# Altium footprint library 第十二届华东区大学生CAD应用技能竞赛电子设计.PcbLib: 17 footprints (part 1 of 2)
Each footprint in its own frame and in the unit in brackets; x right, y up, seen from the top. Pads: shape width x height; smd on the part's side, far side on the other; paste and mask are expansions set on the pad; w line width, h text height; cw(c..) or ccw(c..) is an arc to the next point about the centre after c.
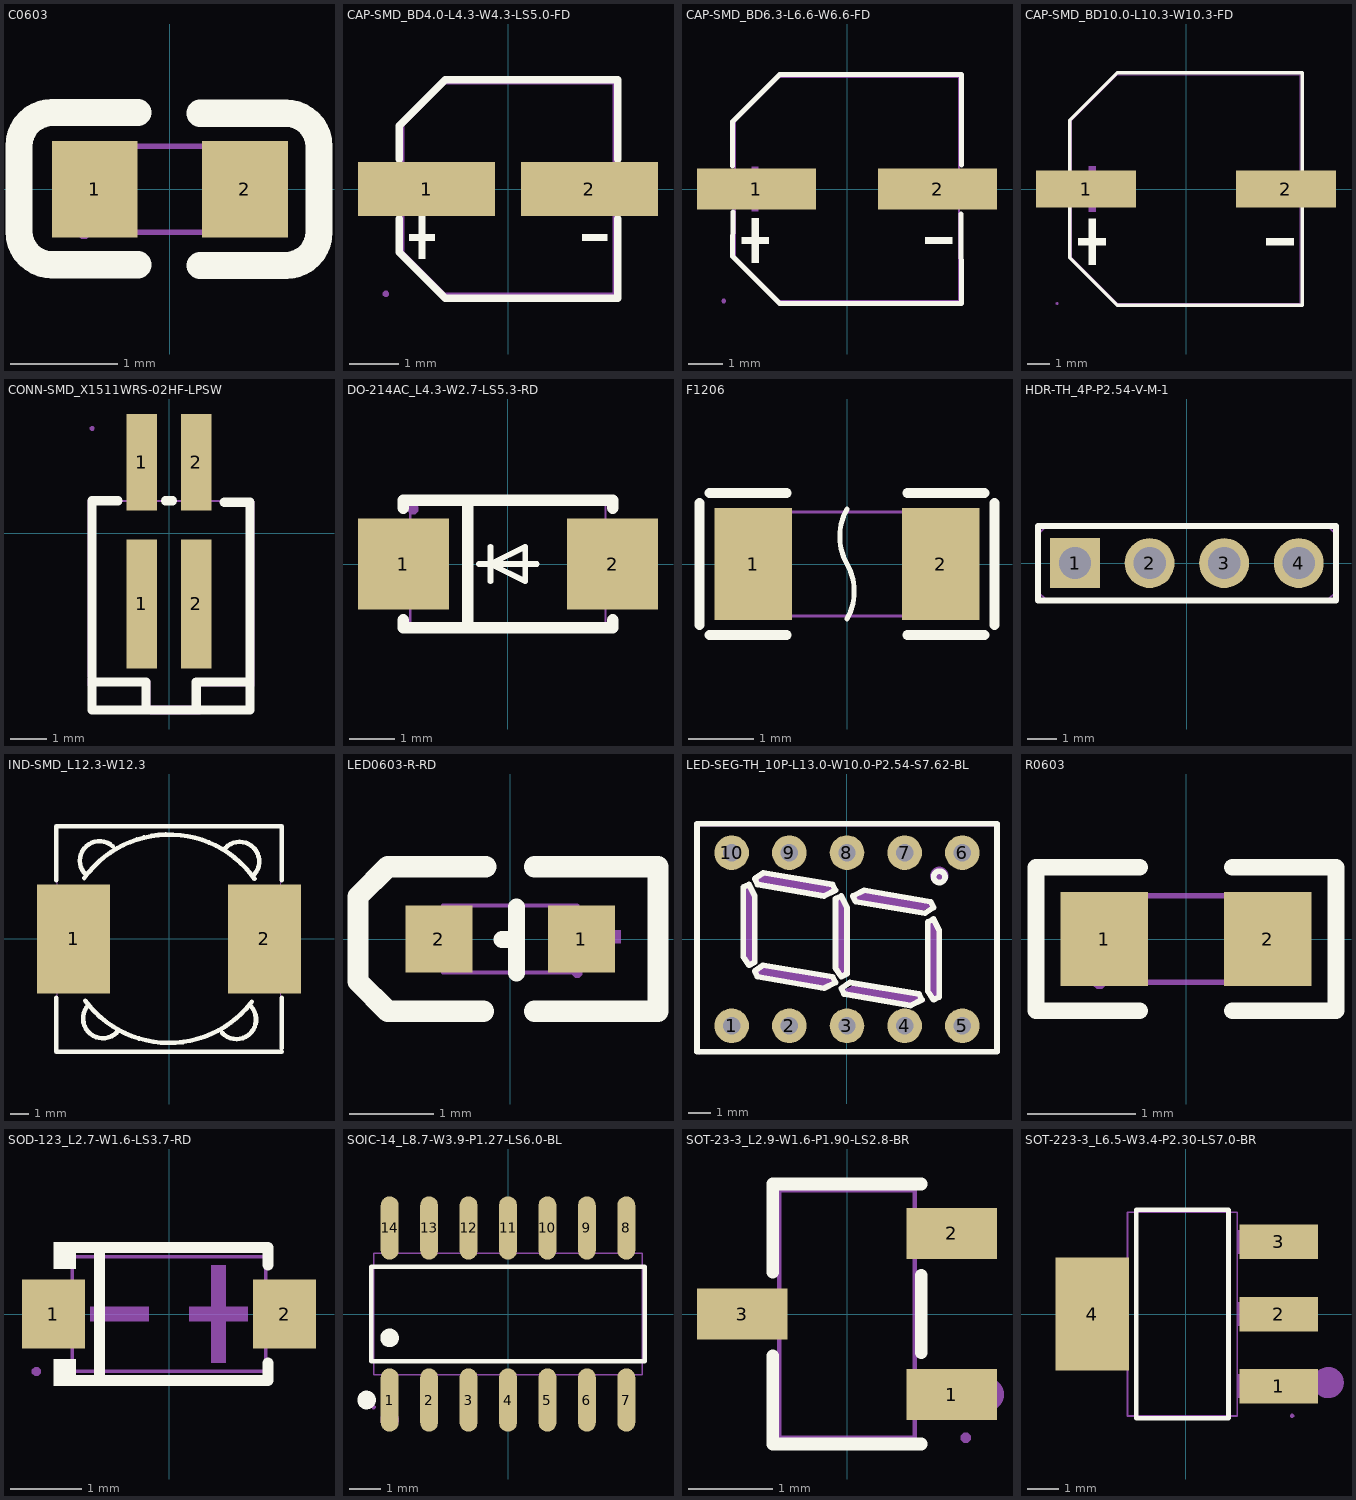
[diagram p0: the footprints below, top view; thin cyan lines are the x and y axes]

## C0603 [mm]
pads (2):
  rect 0.8x0.9 smd mask+0.051: 1(-0.7,0) 2(0.7,0)
Top Overlay:
  lines w0.254: -0.296,-0.704 -1.096,-0.704 cw(c-1.096,-0.394) -1.406,-0.394 -1.405,0.406 cw(c-1.096,0.406) -1.096,0.715 -0.296,0.715 ; 0.28,-0.71 1.08,-0.71 ccw(c1.08,-0.4) 1.39,-0.4 1.39,0.4 ccw(c1.08,0.4) 1.08,0.71 0.28,0.71
Mechanical 15:
  region: -0.74,-0.4 -0.74,-0.375 -0.775,-0.34 -0.825,-0.34 -0.86,-0.375 -0.86,-0.4 -0.86,-0.425 -0.825,-0.46 -0.775,-0.46 -0.74,-0.425
  region: -0.8,-0.4 -0.8,0.4 -0.5,0.4 -0.5,-0.4
  region: 0.8,-0.4 0.8,0.4 0.5,0.4 0.5,-0.4
  lines w0.051: -0.8,-0.4 -0.8,0.4 0.8,0.4 0.8,-0.4 -0.8,-0.4

## CAP-SMD_BD4.0-L4.3-W4.3-LS5.0-FD [mil]
pads (2):
  rect 110.2x43.3 smd mask+2: 1(-65.4,0) 2(65.4,0)
Top Overlay:
  region: 79.9,-36.4 79.9,-41.5 59.6,-41.5 59.6,-36.4
  region: -79.2,-36.4 -79.2,-41.5 -58.9,-41.5 -58.9,-36.4
  region: -71.6,-22 -71.6,-55.9 -66.5,-55.9 -66.5,-22
  lines w6: -87.3,-23.9 -87.3,-50.8 -50.4,-87.6 88,-87.6 88,-23.9 ; -87.3,23.9 -87.3,50.8 -50.4,87.6 88,87.6 88,23.9
Mechanical 6:
  region: 79.9,2.5 79.9,-2.5 59.6,-2.5 59.6,2.5
  region: -79.2,2.5 -79.2,-2.5 -58.9,-2.5 -58.9,2.5
  region: -71.6,16.9 -71.6,-16.9 -66.5,-16.9 -66.5,16.9
Mechanical 15:
  region: -100.5,-84.3 -100.5,-85.29 -99.09,-86.7 -97.11,-86.7 -95.7,-85.29 -95.7,-84.3 -95.7,-83.31 -97.11,-81.9 -99.09,-81.9 -100.5,-83.31
  region: -98.1,12.8 -19.3,12.8 -19.3,-12.8 -98.1,-12.8
  region: 20,12.8 98.8,12.8 98.8,-12.8 20,-12.8
  lines w2: -84.3,-50.4 -50.4,-84.3 85,-84.3 85,85 -50.4,85 -84.3,51.1 -84.3,-50.4

## CAP-SMD_BD6.3-L6.6-W6.6-FD [mm]
pads (2):
  rect 3.5x1.2 smd mask+0.051: 1(-2.67,0) 2(2.67,0)
Top Overlay:
  region: 3.102,-1.419 3.102,-1.617 2.31,-1.617 2.31,-1.419
  region: -3.102,-1.419 -3.102,-1.617 -2.31,-1.617 -2.31,-1.419
  region: -2.805,-0.858 -2.805,-2.178 -2.607,-2.178 -2.607,-0.858
  lines w0.152: -3.376,0.686 -3.376,1.98 -1.98,3.376 3.376,3.376 3.369,0.708 ; -3.362,-0.686 -3.376,-1.981 -1.981,-3.376 3.376,-3.376 3.356,-0.739
Mechanical 6:
  region: 3.102,0.099 3.102,-0.099 2.31,-0.099 2.31,0.099
  region: -3.102,0.099 -3.102,-0.099 -2.31,-0.099 -2.31,0.099
  region: -2.81,0.66 -2.81,-0.66 -2.612,-0.66 -2.612,0.66
Mechanical 15:
  region: -3.634,-3.24 -3.659,-3.24 -3.694,-3.275 -3.694,-3.325 -3.659,-3.36 -3.634,-3.36 -3.609,-3.36 -3.574,-3.325 -3.574,-3.275 -3.609,-3.24
  region: 1.067,0.325 3.667,0.325 3.667,-0.325 1.067,-0.325
  region: -3.634,0.325 -1.034,0.325 -1.034,-0.325 -3.634,-0.325
  lines w0.051: -3.3,-1.98 -1.98,-3.3 3.3,-3.3 3.3,3.3 -1.98,3.3 -3.3,1.98 -3.3,-1.98

## CAP-SMD_BD10.0-L10.3-W10.3-FD [mm]
pads (2):
  rect 4.5x1.65 smd mask+0.051: 1(-4.5,0) 2(4.5,0)
Top Overlay:
  region: 4.841,-2.214 4.841,-2.523 3.605,-2.523 3.605,-2.214
  region: -4.841,-2.214 -4.841,-2.523 -3.605,-2.523 -3.605,-2.214
  region: -4.378,-1.339 -4.378,-3.399 -4.068,-3.399 -4.068,-1.339
  lines w0.152: -5.226,-0.852 -5.226,-3.09 -3.09,-5.226 5.226,-5.226 5.226,-0.852 ; -5.226,0.852 -5.226,3.09 -3.09,5.226 5.226,5.226 5.226,0.852
Mechanical 6:
  region: 4.841,0.155 4.841,-0.155 3.605,-0.155 3.605,0.155
  region: -4.841,0.155 -4.841,-0.155 -3.605,-0.155 -3.605,0.155
  region: -4.378,1.03 -4.378,-1.03 -4.068,-1.03 -4.068,1.03
Mechanical 15:
  region: -5.74,-5.15 -5.74,-5.125 -5.775,-5.09 -5.825,-5.09 -5.86,-5.125 -5.86,-5.15 -5.86,-5.175 -5.825,-5.21 -5.775,-5.21 -5.74,-5.175
  region: -5.8,0.45 -2.3,0.45 -2.3,-0.45 -5.8,-0.45
  region: 2.3,0.45 5.8,0.45 5.8,-0.45 2.3,-0.45
  lines w0.051: -5.15,-3.09 -3.09,-5.15 5.15,-5.15 5.15,5.15 -3.09,5.15 -5.15,3.09 -5.15,-3.09

## CONN-SMD_X1511WRS-02HF-LPSW [mm]
pads (4):
  rect 0.85x3.55 smd mask+0.051: 1(-0.75,-1.95) 2(0.75,-1.95)
  rect 0.85x2.65 smd mask+0.051: 1(-0.75,1.95) 2(0.75,1.95)
Top Overlay:
  lines w0.254: -2.116,-4.87 2.184,-4.87 ; -2.116,-4.826 -2.116,0.889 ; -2.116,-4.101 -0.63,-4.101 -0.63,-4.86 ; -0.094,0.889 0.094,0.889 ; 0.75,-4.72 0.75,-4.1 2.09,-4.1 ; 1.519,0.844 2.229,0.844 2.229,-4.871 ; -2.116,0.889 -1.406,0.889 -2.116,0.889
Mechanical 6:
  region: 2.12,-4 0.71,-4 0.64,-4.07 0.64,-4.98 0.86,-4.98 0.86,-4.22 0.87,-4.21 2.35,-4.21 2.35,-4
  region: 2.34,-3.98 2.34,0.87 2.25,0.96 1.49,0.96 1.44,0.91 1.44,0.79 1.49,0.74 2.11,0.74 2.12,0.73 2.12,-3.99 2.34,-3.99
  region: -2.23,-3.94 -2.23,0.91 -2.14,1 -1.38,1 -1.33,0.95 -1.33,0.83 -1.38,0.78 -2,0.78 -2.01,0.77 -2.01,-3.95 -2.23,-3.95
  region: -2,-3.99 -0.59,-3.99 -0.52,-4.06 -0.52,-4.97 -0.74,-4.97 -0.74,-4.21 -0.75,-4.2 -2.23,-4.2 -2.23,-3.99
  region: -0.51,-4.75 0.64,-4.75 0.64,-4.97 0.63,-4.98 -0.52,-4.98 -0.52,-4.76 -0.53,-4.75
Mechanical 15:
  region: -2.116,2.939 -2.141,2.939 -2.176,2.904 -2.176,2.854 -2.141,2.819 -2.116,2.819 -2.091,2.819 -2.056,2.854 -2.056,2.904 -2.091,2.939
  region: 0.55,2.879 0.95,2.879 0.95,0.779 0.55,0.779
  region: -0.95,2.879 -0.55,2.879 -0.55,0.779 -0.95,0.779
  region: 0.55,-0.7 0.95,-0.7 0.95,-3.2 0.55,-3.2
  region: -0.95,-0.7 -0.55,-0.7 -0.55,-3.2 -0.95,-3.2
  lines w0.051: -2.116,-4.871 -2.116,0.879 2.184,0.879 2.184,-4.871 -2.116,-4.871

## DO-214AC_L4.3-W2.7-LS5.3-RD [mil]
pads (2):
  rect 78.7x78.7 smd mask+2: 1(-90.5,0) 2(90.6,0)
Top Overlay:
  lines w5: -25,0 25,0 ; -15,-15 -15,0 ; -15,15 -15,0 ; -15,0 15,15 15,0 15,-15 -15,0
  lines w10: -90.5,-48.5 -90.5,-55.1 90.6,-55.1 90.6,-48.5 ; -90.5,48.5 -90.5,55.1 90.6,55.1 90.6,48.5 ; -35,-55.1 -35,55.1
Mechanical 6:
  region: 117.9,1.1 63.7,1.1 63.7,5.3 67.7,5.6 117.6,5.5 117.7,5.7 117.7,1.3 117.8,1.2
  region: 89.8,17.6 89.8,-16.7 89.9,-16.8 94.1,-16.8 94.3,-16.6 94.3,17.6 94.1,17.8 89.5,17.8
  region: -117.3,-6.2 -117.5,-5.5 -117.5,3 -63.8,2.9 -63.4,2.1 -63.4,-6.4
Mechanical 15:
  region: -86.9,47.6 -86.9,45.65 -84.15,42.9 -80.25,42.9 -77.5,45.65 -77.5,47.6 -77.5,49.55 -80.25,52.3 -84.15,52.3 -86.9,49.55
  region: -55,22.4 -55,-22.4 -84.6,-22.4 -84.6,22.4
  region: 84.5,22.4 84.5,-22.4 55,-22.4 55,22.4
  lines w2: -84.6,-52.6 -84.6,52.6 84.5,52.6 84.5,-52.6 -84.6,-52.6

## F1206 [mil]
pads (2):
  rect 46.9x68 smd mask+2: 1(-56.9,0) 2(56.9,0)
Top Overlay:
  lines w3: 0,-33.27 ccw(c-28.81,-16.63) 0,0 cw(c28.81,16.63) 0,33.27
  lines w6: -89.3,-37 -89.3,37 ; -83.3,-43 -36.5,-43 ; -83.3,43 -36.5,43 ; 36.5,-43 83.3,-43 ; 36.5,43 83.3,43 ; 89.3,-37 89.3,37
Mechanical 15:
  region: -60.6,-31.5 -60.6,-30.51 -62.01,-29.1 -63.99,-29.1 -65.4,-30.51 -65.4,-31.5 -65.4,-32.49 -63.99,-33.9 -62.01,-33.9 -60.6,-32.49
  region: -63,-31.5 -43.3,-31.5 -43.3,31.5 -63,31.5
  region: 43.3,-31.5 63,-31.5 63,31.5 43.3,31.5
  lines w2: -63,-31.5 63,-31.5 63,31.5 -63,31.5 -63,-31.5

## HDR-TH_4P-P2.54-V-M-1 [mil]
pads (4):
  rect 66.9x66.9 hole 43.3 mask+2: 1(-150,0)
  round 66.9 hole 43.3 mask+2: 2(-50,0) 3(50,0) 4(150,0)
Top Overlay:
  lines w8: -200,-50 200,-50 200,50 -125,50 -200,50 -200,-50
Mechanical 15:
  region: -202.4,-50 -202.4,-50.99 -200.99,-52.4 -199.01,-52.4 -197.6,-50.99 -197.6,-50 -197.6,-49.01 -199.01,-47.6 -200.99,-47.6 -202.4,-49.01
  region: -162.6,12.6 -137.4,12.6 -137.4,-12.6 -162.6,-12.6
  region: -62.6,12.6 -37.4,12.6 -37.4,-12.6 -62.6,-12.6
  region: 37.4,12.6 62.6,12.6 62.6,-12.6 37.4,-12.6
  region: 137.4,12.6 162.6,12.6 162.6,-12.6 137.4,-12.6
  lines w2: -200,-38.2 -188.2,-50 188.2,-50 200,-38.2 200,38.2 188.2,50 -188.2,50 -200,38.2 -200,-38.2

## IND-SMD_L12.3-W12.3 [mil]
pads (2):
  rect 157.5x236.2 smd mask+2: 1(-206.7,0) 2(206.7,0)
Top Overlay:
  lines w10: -244.1,-127.2 -244.1,-244.1 244.1,-244.1 ; -244.1,127.2 -244.1,244.1 244.1,244.1 244.1,127.2 ; -183.72,131.79 cw(c-0.01,0) 185.03,129.92 ; -181.11,-133.86 ccw(c0,0) 179.22,-136.36 ; -179.13,137.96 cw(c-150.46,169.25) -122.05,200.79 ; -178.52,-148.01 ccw(c-143.35,-172.36) -108.6,-197.29 ; 115.24,-203.77 ccw(c146.1,-174.62) 177.16,-145.67 ; 121.55,196.39 cw(c152.85,167.71) 184.38,139.3 ; 244.1,-236.2 244.1,-127.2
Mechanical 15:
  region: -240.2,98.4 -153.5,98.4 -153.5,-98.4 -240.2,-98.4
  region: 153.5,98.4 240.2,98.4 240.2,-98.4 153.5,-98.4
  region: -242.1,-244.5 -241.11,-244.5 -239.7,-243.09 -239.7,-241.11 -241.11,-239.7 -242.1,-239.7 -243.09,-239.7 -244.5,-241.11 -244.5,-243.09 -243.09,-244.5
  lines w2: -242.1,-242.1 242.1,-242.1 242.1,242.1 -242.1,242.1 -242.1,-242.1

## LED0603-R-RD [mm]
pads (2):
  rect 0.8x0.8 smd mask+0.051: 1(0.851,0) 2(-0.851,0)
Top Overlay:
  lines w0.203: -0.099,-0.008 0.076,-0.008 ; 0.076,-0.406 0.076,0.381
  lines w0.254: -0.318,-0.864 -1.46,-0.864 -1.816,-0.508 -1.816,0.508 -1.46,0.864 -0.292,0.864 ; 0.292,-0.864 1.765,-0.864 1.765,0.864 0.292,0.864
Mechanical 6:
  region: 0.66,0.102 1.321,0.102 1.321,-0.051 0.66,-0.051
  region: 0.936,-0.275 0.936,0.385 1.088,0.385 1.088,-0.275
  region: -1.193,0.05 -0.533,0.05 -0.533,-0.103 -1.193,-0.103
Mechanical 15:
  region: 0.74,-0.4 0.74,-0.425 0.775,-0.46 0.825,-0.46 0.86,-0.425 0.86,-0.4 0.86,-0.375 0.825,-0.34 0.775,-0.34 0.74,-0.375
  region: 0.8,0.4 0.8,-0.4 0.5,-0.4 0.5,0.4
  region: -0.8,-0.4 -0.8,0.4 -0.5,0.4 -0.5,-0.4
  lines w0.051: -0.8,-0.4 0.8,-0.4 0.8,0.4 -0.8,0.4 -0.8,-0.4

## LED-SEG-TH_10P-L13.0-W10.0-P2.54-S7.62-BL [mil]
pads (10):
  round 60 hole 30 mask+2: 1(-200,-150) 2(-100,-150) 3(0,-150) 4(100,-150) 5(200,-150) 6(200,150) 7(100,150) 8(0,150) 9(-100,150) 10(-200,150)
Top Overlay:
  lines w10: 150.2,107.9 ccw(c160.04,108) 150.2,108.1 ; -260,-195 -260,200 260,200 260,-195 -260,-195 ; -180,-30 -170,-45 -160,-40 -160,75 -170,95 -180,90 -180,-30 ; -160,-55 -145,-45 -25,-65 -20,-75 -40,-85 -155,-65 -160,-55 ; -160,105 -145,115 -25,95 -20,85 -40,75 -155,95 -160,105 ; -20,-50 -10,-65 0,-60 0,55 -10,75 -20,70 -20,-50 ; -10,-85 5,-75 125,-95 130,-105 110,-115 -5,-95 -10,-85 ; 10,75 30,85 145,65 150,55 135,45 15,65 10,75 ; 140,-90 150,-105 160,-100 160,15 150,35 140,30 140,-90
Mechanical 6:
  circle w15.75: c160,110 r7.87
  region: 149.04,31.36 139.04,26.36 139.04,-88.64 149.04,-103.64 159.04,-98.64 159.04,16.36
  region: -10.96,71.36 -20.95,66.36 -20.95,-48.64 -10.96,-63.64 -0.95,-58.64 -0.95,56.36
  region: -3.96,-87.14 1.04,-97.14 111.05,-117.14 136.04,-107.14 126.05,-97.14 16.05,-77.14
  region: 11.04,77.86 16.05,67.86 126.05,47.86 151.04,57.86 141.04,67.86 31.05,87.86
  region: -158.96,107.86 -153.96,97.86 -43.95,77.86 -18.95,87.86 -28.95,97.86 -138.96,117.86
  region: -160,-55 -155,-65 -45,-85 -20,-75 -30,-65 -140,-45
  region: -170,90 -180,85 -180,-30 -170,-45 -160,-40 -160,75
Mechanical 15:
  drawing of 15 lines, arcs and shapes, not listed

## R0603 [mil]
pads (2):
  rect 31.75x34.02 smd mask+2: 1(-29.66,0) 2(29.66,0)
Top Overlay:
  lines w6: -16.78,-26.01 -54.53,-26.01 -54.53,26.01 -16.78,26.01 ; 16.78,-26.01 54.53,-26.01 54.53,26.01 16.78,26.01
Top Paste:
  region: 47.05,17.72 15.55,17.72 13.58,15.75 13.58,6.77 28.15,6.77 28.15,-6.22 13.58,-6.22 13.58,-15.75 15.55,-17.72 47.05,-17.72 49.02,-15.75 49.02,15.75
  region: -13.98,15.75 -13.98,6.77 -28.94,6.77 -28.94,-6.22 -13.98,-6.22 -13.98,-15.75 -15.94,-17.72 -47.05,-17.72 -49.02,-15.75 -49.02,15.75 -47.05,17.72 -15.94,17.72
Mechanical 15:
  region: -31.5,-18.11 -30.52,-18.11 -29.13,-16.73 -29.13,-14.77 -30.52,-13.39 -31.5,-13.39 -32.47,-13.39 -33.86,-14.77 -33.86,-16.73 -32.47,-18.11
  region: -31.5,-15.75 -31.5,15.75 -19.68,15.75 -19.68,-15.75
  region: 31.5,-15.75 31.5,15.75 19.68,15.75 19.68,-15.75
  lines w2: -31.5,-15.75 -31.5,15.75 31.5,15.75 31.5,-15.75 -31.5,-15.75

## SOD-123_L2.7-W1.6-LS3.7-RD [mil]
pads (2):
  rect 34.6x37.8 smd mask+2: 1(-63.4,0) 2(63.4,0)
Top Overlay:
  region: -51.2,-39.5 -51.2,-24.9 -63.2,-24.9 -63.2,-39.5
  region: -51.2,39.5 -51.2,24.9 -63.2,24.9 -63.2,39.5
  lines w6: -54.2,-36.5 54.2,-36.5 54.2,-26.9 ; -54.2,36.5 54.2,36.5 54.2,26.9 ; -38.1,-36.5 -38.1,36.5
Mechanical 6:
  region: 31.1,26.8 31.1,-26.8 23.1,-26.8 23.1,26.8
  region: 43.2,4 43.2,-4 11,-4 11,4
  region: -43.1,4 -43.1,-4 -11,-4 -11,4
Mechanical 15:
  region: -72.8,12 -52.8,11.8 -52.8,-11.8 -72.8,-12
  region: 52.8,11.8 72.8,12 72.8,-12 52.8,-11.8
  region: -72.8,-29.1 -73.79,-29.1 -75.2,-30.51 -75.2,-32.49 -73.79,-33.9 -72.8,-33.9 -71.81,-33.9 -70.4,-32.49 -70.4,-30.51 -71.81,-29.1
  lines w2: -53,-31.5 53,-31.5 53,31.5 -53,31.5 -53,-31.5

## SOIC-14_L8.7-W3.9-P1.27-LS6.0-BL [mil]
pads (14):
  oval 22.6x80.2 smd mask+2: 1(-150,-109) 2(-100,-109) 3(-50,-109) 4(0,-109) 5(50,-109) 6(100,-109) 7(150,-109) 8(150,109) 9(100,109) 10(50,109) 11(0,109) 12(-50,109) 13(-100,109) 14(-150,109)
Top Overlay:
  circle w11.8: c-179.1,-109 r5.9
  circle w11.8: c-150,-30.3 r5.9
  lines w6: -173.3,-59.9 173.3,-59.9 173.3,59.9 -173.3,59.9 -173.3,-59.9
Mechanical 6:
  circle w11.8: c-150,-133.9 r5.9
Mechanical 15:
  drawing of 33 lines, arcs and shapes, not listed

## SOT-23-3_L2.9-W1.6-P1.90-LS2.8-BR [mm]
pads (3):
  rect 1.07x0.6 smd mask+0.051: 1(1.235,-0.95) 2(1.235,0.95) 3(-1.235,0)
Top Overlay:
  lines w0.152: -0.876,-0.495 -0.876,-1.536 0.876,-1.536 ; -0.876,0.495 -0.876,1.536 0.876,1.536 ; 0.876,-0.455 0.876,0.455
Mechanical 6:
  circle w0.2: c1.651,-0.95 r0.1
Mechanical 15:
  region: -0.96,-0.2 -0.96,0.2 -0.79,0.2 -0.79,-0.2
  region: -0.95,-0.2 -0.95,0.2 -1.4,0.2 -1.4,-0.2
  region: 0.79,0.75 0.79,1.15 0.96,1.15 0.96,0.75
  region: 0.95,0.75 0.95,1.15 1.4,1.15 1.4,0.75
  region: 0.79,-1.15 0.79,-0.75 0.96,-0.75 0.96,-1.15
  region: 0.95,-1.15 0.95,-0.75 1.4,-0.75 1.4,-1.15
  region: 1.4,-1.4 1.375,-1.4 1.34,-1.435 1.34,-1.485 1.375,-1.52 1.4,-1.52 1.425,-1.52 1.46,-1.485 1.46,-1.435 1.425,-1.4
  lines w0.051: -0.8,-1.46 0.8,-1.46 0.8,1.46 -0.8,1.46 -0.8,-1.46

## SOT-223-3_L6.5-W3.4-P2.30-LS7.0-BR [mil]
pads (4):
  rect 98.4x43.3 smd mask+2: 1(116.9,-90.5) 2(116.9,0) 3(116.9,90.6)
  rect 92.1x141.7 smd mask+2: 4(-116.9,0)
Top Overlay:
  lines w6: -61.9,-131 -61.9,131 54,131 54,-131 -61.9,-131
Mechanical 6:
  circle w19.7: c179.2,-86.1 r9.8
Mechanical 15:
  region: 136.3,-127.9 136.3,-126.91 134.89,-125.5 132.91,-125.5 131.5,-126.91 131.5,-127.9 131.5,-128.89 132.91,-130.3 134.89,-130.3 136.3,-128.89
  region: 64.6,75.8 64.6,105.3 104.7,105.3 104.7,75.8
  region: 104.3,75.8 104.3,105.3 133.9,105.3 133.9,75.8
  region: 64.6,-14.8 64.6,14.8 104.7,14.8 104.7,-14.8
  region: 104.3,-14.8 104.3,14.8 133.9,14.8 133.9,-14.8
  region: 64.6,-105.3 64.6,-75.8 104.7,-75.8 104.7,-105.3
  region: 104.3,-105.3 104.3,-75.8 133.9,-75.8 133.9,-105.3
  region: -112.6,-59.1 -112.6,59.1 -72.4,59.1 -72.4,-59.1
  region: -141.7,-59.1 -141.7,59.1 -112.2,59.1 -112.2,-59.1
  lines w2: -72.8,-128 -72.8,128 65,128 65,-128 -72.8,-128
